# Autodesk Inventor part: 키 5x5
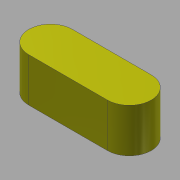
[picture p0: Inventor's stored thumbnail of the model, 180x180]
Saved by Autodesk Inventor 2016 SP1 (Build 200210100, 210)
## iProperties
Created: 2016-04
Part Number: 키 5x5
Document SubType Name: Modeling
Designer: mdu
Density: 7.86 g/cm^3
Mass: 2.54015 g
Surface Area: 2.9781 cm^2
Volume: 0.323175 cm^3
Material: 강철, 연강
Appearance: 강철 - 광택
Author: mdu
Revision Number: 1
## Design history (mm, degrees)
sketch "스케치1"
  geometry: L1 (-4.5, -2.5)-(4.5, -2.5); L2 (4.5, 2.5)-(-4.5, 2.5); A1 r 2.5 centre (4.5, 0) between (4.5, -2.5) and (4.5, 2.5); A2 r 2.5 centre (-4.5, 0) between (-4.5, 2.5) and (-4.5, -2.5); 2 further points
  constraints: 4 end point, 4 point on circle, 4 tangent, 2 centre point, 1 horizontal, 1 horizontal alignment, 1 midpoint, 1 parallel, 1 vertical alignment
  dimensions: "d0" = 5 distance between parallel lines of L1 L2; "d1" = 14 dimension on A1 A2
extrude "돌출1" new body sketch "스케치1" stored distance "d2" = 5; taper "d3" = 0 deg
node "솔리드1"
